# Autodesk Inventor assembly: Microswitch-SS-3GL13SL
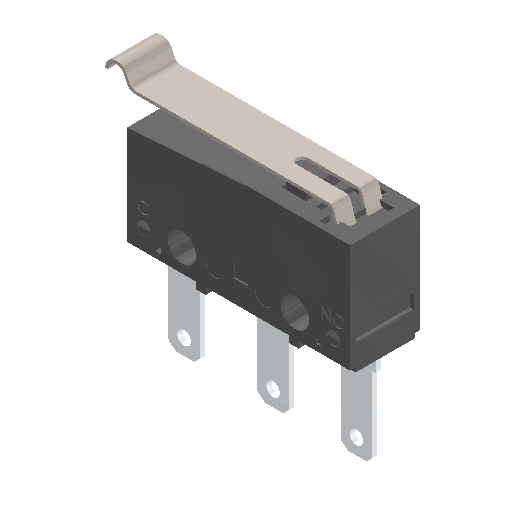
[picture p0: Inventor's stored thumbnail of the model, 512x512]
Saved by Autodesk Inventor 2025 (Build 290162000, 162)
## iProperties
Created: 2018-02
Part Number: Microswitch-SS-3GL13SL
Description: STEP AP214
Document SubType Name: Assembly
Designer: Ryzen5700u
Title: Microswitch-SS-3GL13SL.STEP
Revision Number: ANY
Sending System: SolidWorks 2018
Preprocessor: SwSTEP 2.0
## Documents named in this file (5)
- C:\Users\Ryzen5700u\Desktop\slider_2040\Microswitch-SS-3GL13SL\Microswitch-SS-3GL13SL.iam
- C:\Users\Ryzen5700u\Desktop\slider_2040\Microswitch-SS-3GL13SL\limit-switch-bottomcase.ipt
- C:\Users\Ryzen5700u\Desktop\slider_2040\Microswitch-SS-3GL13SL\limit-switch-top-case.ipt
- C:\Users\Ryzen5700u\Desktop\slider_2040\Microswitch-SS-3GL13SL\pins.ipt
- C:\Users\Ryzen5700u\Desktop\slider_2040\Microswitch-SS-3GL13SL\switch_lever.ipt
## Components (4 placed, 4 different names)
1. limit-switch-bottomcase_1
2. limit-switch-top-case_2 — Coincidente:1
3. pins_3
4. switch_lever_4 — Coincidente:1
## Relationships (1: Mate 1)
- Coincidente:1 [Mate]: limit-switch-top-case_2 ↔ switch_lever_4
